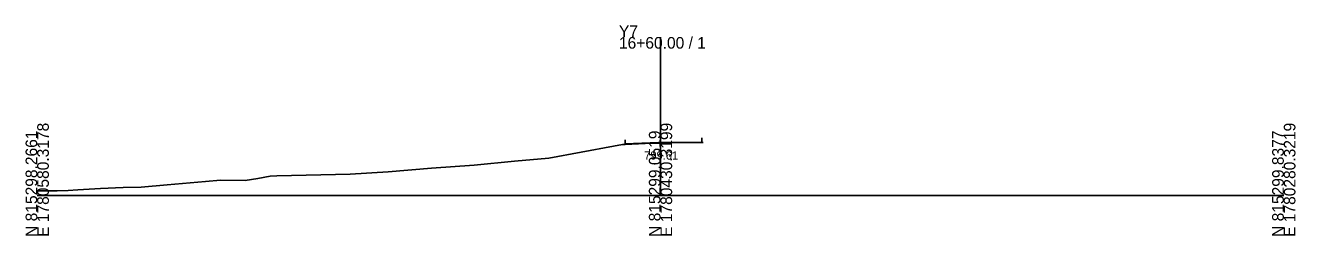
# Model space of a CAD drawing. Extents: x -26 to 2903, y -10 to 5536.
# Drawn here: x 1297.2 to 1602.8, y 1990.3 to 2040.9 of the extents above; entities that cross this region are included whole.
import ezdxf

# ---------------------------------------------------------------- set-up
doc = ezdxf.new("R2010")
doc.units = 0
for name, color, linetype in [('Exist Cross Section Cell', 7, 'Continuous'), ('Exist XS Center Line Elevation Label', 7, 'Continuous'), ('Exist XS Ground Line', 7, 'Continuous'), ('Prop XS EOT Tick Mark', 7, 'Continuous'), ('Prop XS Finish Grade Pavement', 7, 'Continuous')]:
    doc.layers.add(name, color=color, linetype=linetype)

msp = doc.modelspace()

# ---------------------------------------------------------------- linework, layer by layer
at = {"layer": 'Exist Cross Section Cell'}
for p, q in [((1450, 2000), (1450, 2038.13)), ((1300, 2000), (1450, 2000)), ((1450, 2000), (1600, 2000))]:
    msp.add_line(p, q, dxfattribs=at)
at = {"layer": 'Exist XS Ground Line'}
for p, q in [((1423.1, 2008.99), (1438.65, 2011.86)), ((1438.65, 2011.86), (1440.85, 2012.25)), ((1440.85, 2012.25), (1441.49, 2012.28)), ((1441.49, 2012.28), (1449.51, 2012.61)), ((1449.51, 2012.61), (1450, 2012.61)), ((1450, 2012.61), (1459.96, 2012.71)), ((1459.96, 2012.71), (1460.28, 2012.71)), ((1414.83, 2008.22), (1423.1, 2008.99)), ((1375.34, 2005.09), (1384.43, 2005.68)), ((1384.43, 2005.68), (1394.91, 2006.52)), ((1394.91, 2006.52), (1405.14, 2007.31)), ((1405.14, 2007.31), (1414.83, 2008.22)), ((1325, 2001.98), (1331.3, 2002.53)), ((1331.3, 2002.53), (1340.52, 2003.31)), ((1340.52, 2003.31), (1344.13, 2003.63)), ((1344.13, 2003.63), (1350.03, 2003.61)), ((1350.03, 2003.61), (1353.07, 2004.04)), ((1353.07, 2004.04), (1356.06, 2004.65)), ((1356.06, 2004.65), (1357.7, 2004.72)), ((1357.7, 2004.72), (1375.34, 2005.09)), ((1300, 2001.09), (1302.7, 2001.09)), ((1302.7, 2001.09), (1304.81, 2001.13)), ((1304.81, 2001.13), (1307.46, 2001.18)), ((1307.46, 2001.18), (1309.74, 2001.33)), ((1309.74, 2001.33), (1315.24, 2001.69)), ((1315.24, 2001.69), (1320.67, 2001.87)), ((1320.67, 2001.87), (1325, 2001.98))]:
    msp.add_line(p, q, dxfattribs=at)
at = {"layer": 'Prop XS EOT Tick Mark'}
for p, q in [((1441.49, 2012.4), (1441.49, 2013.4)), ((1459.96, 2012.83), (1459.96, 2013.83))]:
    msp.add_line(p, q, dxfattribs=at)
at = {"layer": 'Prop XS Finish Grade Pavement'}
for p, q in [((1441.49, 2012.4), (1449.51, 2012.73)), ((1449.51, 2012.73), (1450, 2012.74)), ((1450, 2012.74), (1459.96, 2012.83))]:
    msp.add_line(p, q, dxfattribs=at)

# ---------------------------------------------------------------- texts
at = {"layer": 'Exist Cross Section Cell'}
for s, p in [('Y7', (1440, 2038.13)), ('16+60.00 / 1', (1440, 2035.33))]:
    msp.add_text(s, height=2.8, dxfattribs=at).set_placement(p)
for s, p in [('N 815298.2661', (1300, 1990)), ('E 1780580.3178', (1302.8, 1990)), ('N 815299.0519', (1450, 1990)), ('E 1780430.3199', (1452.8, 1990)), ('N 815299.8377', (1600, 1990)), ('E 1780280.3219', (1602.8, 1990))]:
    msp.add_text(s, height=2.8, rotation=90, dxfattribs=at).set_placement(p)
at = {"layer": 'Exist XS Center Line Elevation Label'}
msp.add_text('799.61', height=2, dxfattribs=at).set_placement((1446.08, 2008.61))

doc.saveas('drawing.dxf')
